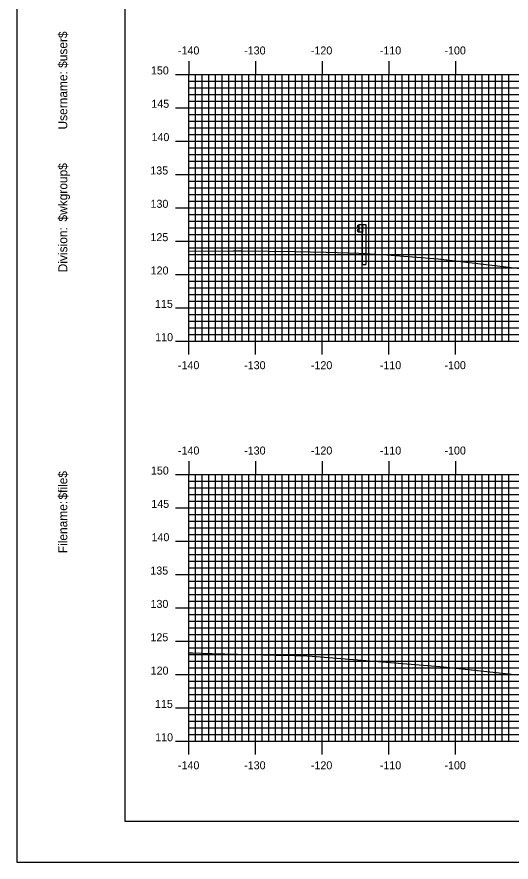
# Model space of a CAD drawing. Extents: x 853721 to 854064, y 364661 to 364881.
# Drawn here: x 853721 to 853795.2, y 364661.3 to 364788 of the extents above; entities that cross this region are included whole.
import ezdxf

# ---------------------------------------------------------------- set-up
doc = ezdxf.new("R2010")
doc.units = 0
for name, color, linetype in [('BORDER', 7, 'Continuous'), ('H_V ANNOTATION', 7, 'Continuous'), ('M_Guardrail', 7, 'Continuous'), ('M_Roadway_Centerline', 7, 'Continuous'), ('MAJOR', 7, 'Continuous'), ('MINOR', 7, 'Continuous'), ('PLOT BOUNDARY', 7, 'Continuous'), ('S_Roadway_Centerline', 7, 'Continuous')]:
    doc.layers.add(name, color=color, linetype=linetype)

msp = doc.modelspace()

# ---------------------------------------------------------------- linework, layer by layer
at = {"layer": 'BORDER'}
msp.add_lwpolyline([(853737.21, 364667.37), (854057.21, 364667.37), (854057.21, 364877.37), (853737.21, 364877.37)], close=True, dxfattribs=at)
at = {"layer": 'M_Guardrail'}
for p, q in [((853772.27, 364756.77), (853772.13, 364756.67)), ((853772.37, 364756.79), (853772.29, 364756.78)), ((853772.37, 364756.86), (853772.86, 364756.86)), ((853772.37, 364755.7), (853772.37, 364756.86)), ((853772.86, 364756.86), (853773.35, 364756.86)), ((853772.86, 364756.86), (853772.86, 364755.7)), ((853773.35, 364756.86), (853773.35, 364750.86)), ((853772.13, 364756.53), (853772.33, 364756.39)), ((853772.33, 364756.17), (853772.13, 364756.04)), ((853772.13, 364755.89), (853772.27, 364755.79)), ((853772.29, 364755.79), (853772.37, 364755.77)), ((853772.36, 364756.33), (853772.36, 364756.24)), ((853772.86, 364755.7), (853772.37, 364755.7)), ((853772.86, 364750.86), (853772.86, 364755.7)), ((853772.86, 364750.86), (853773.35, 364750.86))]:
    msp.add_line(p, q, dxfattribs=at)
for centre, major_axis, start_param, end_param in [((853772.18, 364756.6), (-0.0877, 0), 5.323254, 7.243116), ((853772.3, 364756.74), (-0.0417, 0), 4.886922, 5.323254), ((853772.18, 364755.96), (-0.0877, 0), 5.323254, 7.243116), ((853772.3, 364755.83), (-0.0417, 0), 0.959931, 1.396263), ((853772.28, 364756.33), (0.0789, 0), 0, 0.959931), ((853772.28, 364756.24), (0.0789, 0), 5.323254, 6.283185)]:
    msp.add_ellipse(centre, major_axis=major_axis, ratio=0.995501, start_param=start_param, end_param=end_param, dxfattribs=at)
at = {"layer": 'MAJOR'}
for p, q in [((853746.81, 364781.37), (853746.81, 364779.37)), ((853756.81, 364781.37), (853756.81, 364779.37)), ((853766.81, 364781.37), (853766.81, 364779.37)), ((853776.81, 364781.37), (853776.81, 364779.37)), ((853786.81, 364781.37), (853786.81, 364779.37)), ((853744.8, 364779.37), (853746.81, 364779.37)), ((853746.81, 364779.37), (854026.81, 364779.37)), ((853746.81, 364739.37), (853746.81, 364779.37)), ((853746.81, 364739.37), (853746.81, 364779.37)), ((853746.81, 364779.37), (854026.81, 364779.37)), ((853756.81, 364739.37), (853756.81, 364779.37)), ((853766.81, 364739.37), (853766.81, 364779.37)), ((853776.81, 364739.37), (853776.81, 364779.37)), ((853786.81, 364739.37), (853786.81, 364779.37)), ((853744.8, 364774.37), (853746.81, 364774.37)), ((853746.81, 364774.37), (854026.81, 364774.37)), ((853744.8, 364769.37), (853746.81, 364769.37)), ((853746.81, 364769.37), (854026.81, 364769.37)), ((853744.8, 364764.37), (853746.81, 364764.37)), ((853746.81, 364764.37), (854026.81, 364764.37)), ((853744.8, 364759.37), (853746.81, 364759.37)), ((853746.81, 364759.37), (854026.81, 364759.37)), ((853744.8, 364754.37), (853746.81, 364754.37)), ((853746.81, 364754.37), (854026.81, 364754.37)), ((853744.8, 364749.37), (853746.81, 364749.37)), ((853746.81, 364749.37), (854026.81, 364749.37)), ((853744.8, 364744.37), (853746.81, 364744.37)), ((853746.81, 364744.37), (854026.81, 364744.37)), ((853744.8, 364739.37), (853746.81, 364739.37)), ((853746.81, 364739.37), (854026.81, 364739.37)), ((853746.81, 364739.37), (854026.81, 364739.37)), ((853746.81, 364737.37), (853746.81, 364739.37)), ((853756.81, 364737.37), (853756.81, 364739.37)), ((853766.81, 364737.37), (853766.81, 364739.37)), ((853776.81, 364737.37), (853776.81, 364739.37)), ((853786.81, 364737.37), (853786.81, 364739.37)), ((853746.81, 364721.37), (853746.81, 364719.37)), ((853756.81, 364721.37), (853756.81, 364719.37)), ((853766.81, 364721.37), (853766.81, 364719.37)), ((853776.81, 364721.37), (853776.81, 364719.37)), ((853786.81, 364721.37), (853786.81, 364719.37)), ((853744.8, 364719.37), (853746.81, 364719.37)), ((853746.81, 364719.37), (854026.81, 364719.37)), ((853746.81, 364679.37), (853746.81, 364719.37)), ((853746.81, 364679.37), (853746.81, 364719.37)), ((853746.81, 364719.37), (854026.81, 364719.37)), ((853756.81, 364679.37), (853756.81, 364719.37)), ((853766.81, 364679.37), (853766.81, 364719.37)), ((853776.81, 364679.37), (853776.81, 364719.37)), ((853786.81, 364679.37), (853786.81, 364719.37)), ((853744.8, 364714.37), (853746.81, 364714.37)), ((853746.81, 364714.37), (854026.81, 364714.37)), ((853744.8, 364709.37), (853746.81, 364709.37)), ((853746.81, 364709.37), (854026.81, 364709.37)), ((853744.8, 364704.37), (853746.81, 364704.37)), ((853746.81, 364704.37), (854026.81, 364704.37)), ((853744.8, 364699.37), (853746.81, 364699.37)), ((853746.81, 364699.37), (854026.81, 364699.37)), ((853744.8, 364694.37), (853746.81, 364694.37)), ((853746.81, 364694.37), (854026.81, 364694.37)), ((853744.8, 364689.37), (853746.81, 364689.37)), ((853746.81, 364689.37), (854026.81, 364689.37)), ((853744.8, 364684.37), (853746.81, 364684.37)), ((853746.81, 364684.37), (854026.81, 364684.37)), ((853744.8, 364679.37), (853746.81, 364679.37)), ((853746.81, 364679.37), (854026.81, 364679.37)), ((853746.81, 364679.37), (854026.81, 364679.37)), ((853746.81, 364677.37), (853746.81, 364679.37)), ((853756.81, 364677.37), (853756.81, 364679.37)), ((853766.81, 364677.37), (853766.81, 364679.37)), ((853776.81, 364677.37), (853776.81, 364679.37)), ((853786.81, 364677.37), (853786.81, 364679.37))]:
    msp.add_line(p, q, dxfattribs=at)
at = {"layer": 'MINOR'}
for p, q in [((853746.81, 364778.37), (854026.81, 364778.37)), ((853746.81, 364778.37), (853748.81, 364778.37)), ((853747.81, 364739.37), (853747.81, 364779.37)), ((853748.81, 364739.37), (853748.81, 364779.37)), ((853749.81, 364739.37), (853749.81, 364779.37)), ((853750.81, 364739.37), (853750.81, 364779.37)), ((853751.81, 364739.37), (853751.81, 364779.37)), ((853752.81, 364739.37), (853752.81, 364779.37)), ((853753.81, 364739.37), (853753.81, 364779.37)), ((853754.81, 364739.37), (853754.81, 364779.37)), ((853755.81, 364739.37), (853755.81, 364779.37)), ((853757.81, 364739.37), (853757.81, 364779.37)), ((853758.81, 364739.37), (853758.81, 364779.37)), ((853759.81, 364739.37), (853759.81, 364779.37)), ((853760.81, 364739.37), (853760.81, 364779.37)), ((853761.81, 364739.37), (853761.81, 364779.37)), ((853762.81, 364739.37), (853762.81, 364779.37)), ((853763.81, 364739.37), (853763.81, 364779.37)), ((853764.81, 364739.37), (853764.81, 364779.37)), ((853765.81, 364739.37), (853765.81, 364779.37)), ((853767.81, 364739.37), (853767.81, 364779.37)), ((853768.81, 364739.37), (853768.81, 364779.37)), ((853769.81, 364739.37), (853769.81, 364779.37)), ((853770.81, 364739.37), (853770.81, 364779.37)), ((853771.81, 364739.37), (853771.81, 364779.37)), ((853772.81, 364739.37), (853772.81, 364779.37)), ((853773.81, 364739.37), (853773.81, 364779.37)), ((853774.81, 364739.37), (853774.81, 364779.37)), ((853775.81, 364739.37), (853775.81, 364779.37)), ((853777.81, 364739.37), (853777.81, 364779.37)), ((853778.81, 364739.37), (853778.81, 364779.37)), ((853779.81, 364739.37), (853779.81, 364779.37)), ((853780.81, 364739.37), (853780.81, 364779.37)), ((853781.81, 364739.37), (853781.81, 364779.37)), ((853782.81, 364739.37), (853782.81, 364779.37)), ((853783.81, 364739.37), (853783.81, 364779.37)), ((853784.81, 364739.37), (853784.81, 364779.37)), ((853785.81, 364739.37), (853785.81, 364779.37)), ((853787.81, 364739.37), (853787.81, 364779.37)), ((853788.81, 364739.37), (853788.81, 364779.37)), ((853789.81, 364739.37), (853789.81, 364779.37)), ((853790.81, 364739.37), (853790.81, 364779.37)), ((853791.81, 364739.37), (853791.81, 364779.37)), ((853792.81, 364739.37), (853792.81, 364779.37)), ((853793.81, 364739.37), (853793.81, 364779.37)), ((853794.81, 364739.37), (853794.81, 364779.37)), ((853746.81, 364777.37), (854026.81, 364777.37)), ((853746.81, 364777.37), (853748.81, 364777.37)), ((853746.81, 364776.37), (854026.81, 364776.37)), ((853746.81, 364776.37), (853748.81, 364776.37)), ((853746.81, 364775.37), (854026.81, 364775.37)), ((853746.81, 364775.37), (853748.81, 364775.37)), ((853746.81, 364773.37), (854026.81, 364773.37)), ((853746.81, 364773.37), (853748.81, 364773.37)), ((853746.81, 364772.37), (854026.81, 364772.37)), ((853746.81, 364772.37), (853748.81, 364772.37)), ((853746.81, 364771.37), (854026.81, 364771.37)), ((853746.81, 364771.37), (853748.81, 364771.37)), ((853746.81, 364770.37), (854026.81, 364770.37)), ((853746.81, 364770.37), (853748.81, 364770.37)), ((853746.81, 364768.37), (854026.81, 364768.37)), ((853746.81, 364768.37), (853748.81, 364768.37)), ((853746.81, 364767.37), (854026.81, 364767.37)), ((853746.81, 364767.37), (853748.81, 364767.37)), ((853746.81, 364766.37), (854026.81, 364766.37)), ((853746.81, 364766.37), (853748.81, 364766.37)), ((853746.81, 364765.37), (854026.81, 364765.37)), ((853746.81, 364765.37), (853748.81, 364765.37)), ((853746.81, 364763.37), (854026.81, 364763.37)), ((853746.81, 364763.37), (853748.81, 364763.37)), ((853746.81, 364762.37), (854026.81, 364762.37)), ((853746.81, 364762.37), (853748.81, 364762.37)), ((853746.81, 364761.37), (854026.81, 364761.37)), ((853746.81, 364761.37), (853748.81, 364761.37)), ((853746.81, 364760.37), (854026.81, 364760.37)), ((853746.81, 364760.37), (853748.81, 364760.37)), ((853746.81, 364758.37), (854026.81, 364758.37)), ((853746.81, 364758.37), (853748.81, 364758.37)), ((853746.81, 364757.37), (854026.81, 364757.37)), ((853746.81, 364757.37), (853748.81, 364757.37)), ((853746.81, 364756.37), (854026.81, 364756.37)), ((853746.81, 364756.37), (853748.81, 364756.37)), ((853746.81, 364755.37), (854026.81, 364755.37)), ((853746.81, 364755.37), (853748.81, 364755.37)), ((853746.81, 364753.37), (854026.81, 364753.37)), ((853746.81, 364753.37), (853748.81, 364753.37)), ((853746.81, 364752.37), (854026.81, 364752.37)), ((853746.81, 364752.37), (853748.81, 364752.37)), ((853746.81, 364751.37), (854026.81, 364751.37)), ((853746.81, 364751.37), (853748.81, 364751.37)), ((853746.81, 364750.37), (854026.81, 364750.37)), ((853746.81, 364750.37), (853748.81, 364750.37)), ((853746.81, 364748.37), (854026.81, 364748.37)), ((853746.81, 364748.37), (853748.81, 364748.37)), ((853746.81, 364747.37), (854026.81, 364747.37)), ((853746.81, 364747.37), (853748.81, 364747.37)), ((853746.81, 364746.37), (854026.81, 364746.37)), ((853746.81, 364746.37), (853748.81, 364746.37)), ((853746.81, 364745.37), (854026.81, 364745.37)), ((853746.81, 364745.37), (853748.81, 364745.37)), ((853746.81, 364743.37), (854026.81, 364743.37)), ((853746.81, 364743.37), (853748.81, 364743.37)), ((853746.81, 364742.37), (854026.81, 364742.37)), ((853746.81, 364742.37), (853748.81, 364742.37)), ((853746.81, 364741.37), (854026.81, 364741.37)), ((853746.81, 364741.37), (853748.81, 364741.37)), ((853746.81, 364740.37), (854026.81, 364740.37)), ((853746.81, 364740.37), (853748.81, 364740.37)), ((853747.81, 364679.37), (853747.81, 364719.37)), ((853748.81, 364679.37), (853748.81, 364719.37)), ((853749.81, 364679.37), (853749.81, 364719.37)), ((853750.81, 364679.37), (853750.81, 364719.37)), ((853751.81, 364679.37), (853751.81, 364719.37)), ((853752.81, 364679.37), (853752.81, 364719.37)), ((853753.81, 364679.37), (853753.81, 364719.37)), ((853754.81, 364679.37), (853754.81, 364719.37)), ((853755.81, 364679.37), (853755.81, 364719.37)), ((853757.81, 364679.37), (853757.81, 364719.37)), ((853758.81, 364679.37), (853758.81, 364719.37)), ((853759.81, 364679.37), (853759.81, 364719.37)), ((853760.81, 364679.37), (853760.81, 364719.37)), ((853761.81, 364679.37), (853761.81, 364719.37)), ((853762.81, 364679.37), (853762.81, 364719.37)), ((853763.81, 364679.37), (853763.81, 364719.37)), ((853764.81, 364679.37), (853764.81, 364719.37)), ((853765.81, 364679.37), (853765.81, 364719.37)), ((853767.81, 364679.37), (853767.81, 364719.37)), ((853768.81, 364679.37), (853768.81, 364719.37)), ((853769.81, 364679.37), (853769.81, 364719.37)), ((853770.81, 364679.37), (853770.81, 364719.37)), ((853771.81, 364679.37), (853771.81, 364719.37)), ((853772.81, 364679.37), (853772.81, 364719.37)), ((853773.81, 364679.37), (853773.81, 364719.37)), ((853774.81, 364679.37), (853774.81, 364719.37)), ((853775.81, 364679.37), (853775.81, 364719.37)), ((853777.81, 364679.37), (853777.81, 364719.37)), ((853778.81, 364679.37), (853778.81, 364719.37)), ((853779.81, 364679.37), (853779.81, 364719.37)), ((853780.81, 364679.37), (853780.81, 364719.37)), ((853781.81, 364679.37), (853781.81, 364719.37)), ((853782.81, 364679.37), (853782.81, 364719.37)), ((853783.81, 364679.37), (853783.81, 364719.37)), ((853784.81, 364679.37), (853784.81, 364719.37)), ((853785.81, 364679.37), (853785.81, 364719.37)), ((853787.81, 364679.37), (853787.81, 364719.37)), ((853788.81, 364679.37), (853788.81, 364719.37)), ((853789.81, 364679.37), (853789.81, 364719.37)), ((853790.81, 364679.37), (853790.81, 364719.37)), ((853791.81, 364679.37), (853791.81, 364719.37)), ((853792.81, 364679.37), (853792.81, 364719.37)), ((853793.81, 364679.37), (853793.81, 364719.37)), ((853794.81, 364679.37), (853794.81, 364719.37)), ((853746.81, 364718.37), (854026.81, 364718.37)), ((853746.81, 364718.37), (853748.81, 364718.37)), ((853746.81, 364717.37), (854026.81, 364717.37)), ((853746.81, 364717.37), (853748.81, 364717.37)), ((853746.81, 364716.37), (854026.81, 364716.37)), ((853746.81, 364716.37), (853748.81, 364716.37)), ((853746.81, 364715.37), (854026.81, 364715.37)), ((853746.81, 364715.37), (853748.81, 364715.37)), ((853746.81, 364713.37), (854026.81, 364713.37)), ((853746.81, 364713.37), (853748.81, 364713.37)), ((853746.81, 364712.37), (854026.81, 364712.37)), ((853746.81, 364712.37), (853748.81, 364712.37)), ((853746.81, 364711.37), (854026.81, 364711.37)), ((853746.81, 364711.37), (853748.81, 364711.37)), ((853746.81, 364710.37), (854026.81, 364710.37)), ((853746.81, 364710.37), (853748.81, 364710.37)), ((853746.81, 364708.37), (854026.81, 364708.37)), ((853746.81, 364708.37), (853748.81, 364708.37)), ((853746.81, 364707.37), (854026.81, 364707.37)), ((853746.81, 364707.37), (853748.81, 364707.37)), ((853746.81, 364706.37), (854026.81, 364706.37)), ((853746.81, 364706.37), (853748.81, 364706.37)), ((853746.81, 364705.37), (854026.81, 364705.37)), ((853746.81, 364705.37), (853748.81, 364705.37)), ((853746.81, 364703.37), (854026.81, 364703.37)), ((853746.81, 364703.37), (853748.81, 364703.37)), ((853746.81, 364702.37), (854026.81, 364702.37)), ((853746.81, 364702.37), (853748.81, 364702.37)), ((853746.81, 364701.37), (854026.81, 364701.37)), ((853746.81, 364701.37), (853748.81, 364701.37)), ((853746.81, 364700.37), (854026.81, 364700.37)), ((853746.81, 364700.37), (853748.81, 364700.37)), ((853746.81, 364698.37), (854026.81, 364698.37)), ((853746.81, 364698.37), (853748.81, 364698.37)), ((853746.81, 364697.37), (854026.81, 364697.37)), ((853746.81, 364697.37), (853748.81, 364697.37)), ((853746.81, 364696.37), (854026.81, 364696.37)), ((853746.81, 364696.37), (853748.81, 364696.37)), ((853746.81, 364695.37), (854026.81, 364695.37)), ((853746.81, 364695.37), (853748.81, 364695.37)), ((853746.81, 364693.37), (854026.81, 364693.37)), ((853746.81, 364693.37), (853748.81, 364693.37)), ((853746.81, 364692.37), (854026.81, 364692.37)), ((853746.81, 364692.37), (853748.81, 364692.37)), ((853746.81, 364691.37), (854026.81, 364691.37)), ((853746.81, 364691.37), (853748.81, 364691.37)), ((853746.81, 364690.37), (854026.81, 364690.37)), ((853746.81, 364690.37), (853748.81, 364690.37)), ((853746.81, 364688.37), (854026.81, 364688.37)), ((853746.81, 364688.37), (853748.81, 364688.37)), ((853746.81, 364687.37), (854026.81, 364687.37)), ((853746.81, 364687.37), (853748.81, 364687.37)), ((853746.81, 364686.37), (854026.81, 364686.37)), ((853746.81, 364686.37), (853748.81, 364686.37)), ((853746.81, 364685.37), (854026.81, 364685.37)), ((853746.81, 364685.37), (853748.81, 364685.37)), ((853746.81, 364683.37), (854026.81, 364683.37)), ((853746.81, 364683.37), (853748.81, 364683.37)), ((853746.81, 364682.37), (854026.81, 364682.37)), ((853746.81, 364682.37), (853748.81, 364682.37)), ((853746.81, 364681.37), (854026.81, 364681.37)), ((853746.81, 364681.37), (853748.81, 364681.37)), ((853746.81, 364680.37), (854026.81, 364680.37)), ((853746.81, 364680.37), (853748.81, 364680.37))]:
    msp.add_line(p, q, dxfattribs=at)
at = {"layer": 'PLOT BOUNDARY'}
msp.add_lwpolyline([(853721.02, 364661.25), (854061.02, 364661.25), (854061.02, 364881.25), (853721.02, 364881.25)], close=True, dxfattribs=at)
at = {"layer": 'S_Roadway_Centerline'}
for points in [[(853746.81, 364752.85), (853753.45, 364752.93), (853754.04, 364752.93), (853754.77, 364752.93), (853762.69, 364752.84), (853767.43, 364752.74), (853772.33, 364752.55), (853776.52, 364752.31), (853784.21, 364751.73), (853799.5, 364749.93)], [(853746.81, 364692.61), (853747.3, 364692.61), (853747.36, 364692.61), (853750.27, 364692.52), (853759.89, 364692.3), (853762.68, 364692.25), (853763.8, 364692.22), (853765.3, 364692.12), (853784.48, 364690.57), (853784.73, 364690.55), (853785.01, 364690.52), (853796.19, 364689.32)]]:
    msp.add_lwpolyline(points, dxfattribs=at)

# ---------------------------------------------------------------- texts
at = {"layer": 'BORDER'}
for s, p in [('$user$', (853728.58, 364780.35)), ('Username:', (853728.58, 364771.11)), ('$wkgroup$', (853728.58, 364757.31)), ('Division:', (853728.58, 364749.7)), ('$file$', (853728.58, 364715.62)), ('Filename:', (853728.58, 364707.57))]:
    msp.add_text(s, height=1.339, rotation=90, dxfattribs=at).set_placement(p)
at = {"layer": 'H_V ANNOTATION'}
for s, p in [('-140', (853745.19, 364782.37)), ('-130', (853755.12, 364782.37)), ('-120', (853765.13, 364782.37)), ('-110', (853775.47, 364782.37)), ('-100', (853785.17, 364782.37)), ('150', (853741.13, 364779.37)), ('145', (853741.19, 364774.37)), ('140', (853741.22, 364769.37)), ('135', (853741.04, 364764.37)), ('130', (853741.07, 364759.37)), ('125', (853741.06, 364754.37)), ('120', (853741.09, 364749.37)), ('115', (853741.74, 364744.37)), ('110', (853741.77, 364739.37)), ('-140', (853745.19, 364735.17)), ('-130', (853755.12, 364735.17)), ('-120', (853765.13, 364735.17)), ('-110', (853775.47, 364735.17)), ('-100', (853785.17, 364735.17)), ('-140', (853745.19, 364722.37)), ('-130', (853755.12, 364722.37)), ('-120', (853765.13, 364722.37)), ('-110', (853775.47, 364722.37)), ('-100', (853785.17, 364722.37)), ('150', (853741.13, 364719.37)), ('145', (853741.19, 364714.37)), ('140', (853741.22, 364709.37)), ('135', (853741.04, 364704.37)), ('130', (853741.07, 364699.37)), ('125', (853741.06, 364694.37)), ('120', (853741.09, 364689.37)), ('115', (853741.74, 364684.37)), ('110', (853741.77, 364679.37)), ('-140', (853745.19, 364675.17)), ('-130', (853755.12, 364675.17)), ('-120', (853765.13, 364675.17)), ('-110', (853775.47, 364675.17)), ('-100', (853785.17, 364675.17))]:
    msp.add_text(s, height=1.2, dxfattribs=at).set_placement(p)
at = {"layer": 'M_Roadway_Centerline'}
for s, p in [('C', (853754.03, 364752.93)), ('L', (853754.04, 364752.93)), ('C', (853747.36, 364692.61)), ('L', (853747.36, 364692.61))]:
    msp.add_text(s, height=0.0146, dxfattribs=at).set_placement(p)
at = {"layer": 'MAJOR'}
for p in [(853746.8, 364739.37), (853746.8, 364679.37)]:
    msp.add_text('-', height=0.012, dxfattribs=at).set_placement(p)

doc.saveas('drawing.dxf')
